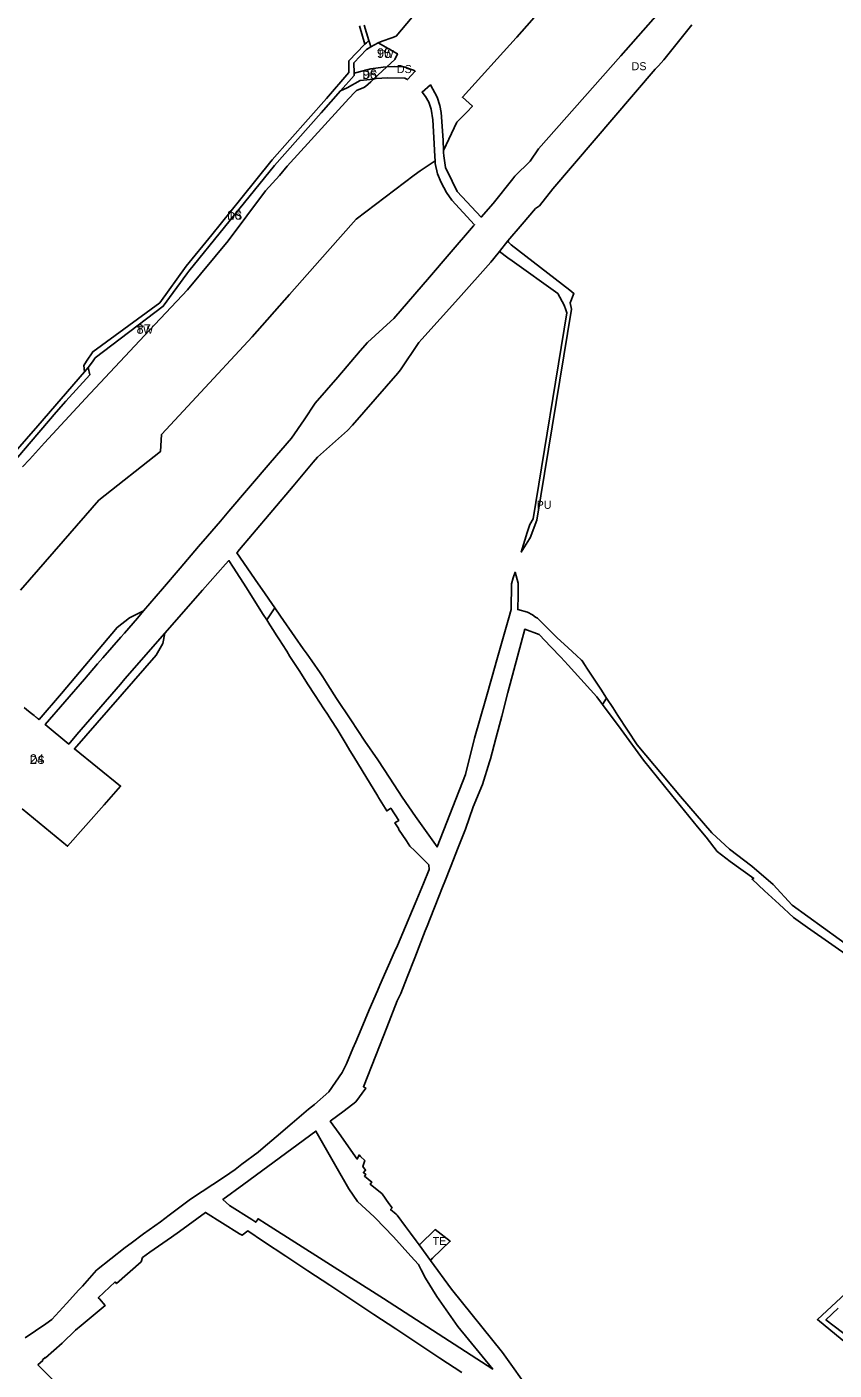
# Model space of a CAD drawing. Extents: x -537034 to -534353, y -1176562 to -1173176.
# Drawn here: x -535789 to -535284, y -1175264 to -1174424 of the extents above; entities that cross this region are included whole.
import ezdxf

# ---------------------------------------------------------------- set-up
doc = ezdxf.new("R2010")
doc.units = 0
for name, color, linetype in [('90320013', 7, 'Continuous'), ('90320023', 7, 'Continuous'), ('90330013', 7, 'Continuous'), ('90390023', 7, 'Continuous'), ('90400013', 7, 'Continuous'), ('90450013', 7, 'Continuous'), ('ID_navrh', 7, 'Continuous')]:
    doc.layers.add(name, color=color, linetype=linetype)

msp = doc.modelspace()

# ---------------------------------------------------------------- linework, layer by layer
at = {"layer": '90320013'}
for points in [[(-535373.49, -1174423.05), (-535390.89, -1174444.84), (-535394.37, -1174448.56), (-535396.32, -1174450.64), (-535460.36, -1174525.57), (-535468.67, -1174536.04), (-535471.15, -1174537.77), (-535479.55, -1174547.52), (-535488.59, -1174558.02), (-535493.78, -1174564.65), (-535497.25, -1174569.07), (-535499.11, -1174571.32), (-535519.4, -1174593.91), (-535542.3, -1174619.4), (-535544.16, -1174621.48), (-535555.54, -1174638.64), (-535557.37, -1174640.72), (-535585.75, -1174673.06), (-535588.72, -1174676.44), (-535607.59, -1174693.18), (-535610.27, -1174696.36), (-535622.79, -1174711.22), (-535648.09, -1174741.22), (-535656.23, -1174750.88), (-535657.72, -1174752.65), (-535658.06, -1174752.99), (-535644.71, -1174772.21), (-535642.13, -1174775.92), (-535634.25, -1174787.25), (-535639.25, -1174794.86), (-535641.48, -1174791.36), (-535642.89, -1174789.15), (-535652.03, -1174774.81), (-535656.11, -1174768.41), (-535660.29, -1174761.86), (-535662.91, -1174757.75), (-535665.15, -1174759.95), (-535679.38, -1174776.21), (-535702.92, -1174803.1), (-535727.94, -1174831.68), (-535730.8, -1174834.95), (-535757.93, -1174866.46), (-535763.09, -1174872.45), (-535777.81, -1174860.26), (-535753.32, -1174831.89), (-535745.05, -1174822.31), (-535741.81, -1174818.61), (-535730.54, -1174805.7), (-535728.28, -1174803.12), (-535720.01, -1174793.65), (-535716.26, -1174789.26), (-535704.49, -1174775.48), (-535693.46, -1174762.57), (-535681.87, -1174749), (-535676.25, -1174742.42), (-535670.89, -1174736.17), (-535668.24, -1174733.08), (-535662.9, -1174726.86), (-535637.08, -1174696.76), (-535623.74, -1174681.22), (-535615.96, -1174669.8), (-535608.9, -1174659.44), (-535594.83, -1174643.09), (-535580.76, -1174626.75), (-535576.31, -1174621.58), (-535561.88, -1174608.41), (-535559.75, -1174606.46), (-535537.48, -1174580.61), (-535525.17, -1174566.32), (-535509.96, -1174548.62), (-535509.32, -1174547.89), (-535523.54, -1174532.47), (-535526.78, -1174527.73), (-535530.21, -1174521.58), (-535532.6, -1174516.01), (-535533.96, -1174509.74), (-535534.01, -1174508.81), (-535534.06, -1174508.07), (-535534.22, -1174505.2), (-535534.89, -1174493.42), (-535535.53, -1174482.27), (-535536.55, -1174475.76), (-535537.97, -1174471.29), (-535539.98, -1174467.86), (-535542.19, -1174465.03), (-535536.95, -1174460.5), (-535532.81, -1174468.18), (-535531.1, -1174473.31), (-535530.16, -1174477.81), (-535528.98, -1174495.04), (-535528.74, -1174501.56), (-535528.7, -1174502.71), (-535528.62, -1174504.76), (-535527.55, -1174512.19), (-535523.26, -1174520.67), (-535520.16, -1174527.13), (-535505.18, -1174543.16), (-535497.79, -1174534.64), (-535485.44, -1174519.17), (-535484.19, -1174517.6), (-535474.62, -1174508.21), (-535469.32, -1174500.48), (-535417.86, -1174442.33), (-535383.65, -1174403.46)], [(-535233.44, -1175034.37), (-535301.06, -1174986.97), (-535309.83, -1174980.83), (-535318.81, -1174972.57), (-535327.96, -1174964.15), (-535335.79, -1174956.95), (-535334.8, -1174956.49), (-535349.55, -1174945.71), (-535357.59, -1174939.56), (-535364.5, -1174930.66), (-535369.87, -1174924.08), (-535386.22, -1174904.06), (-535403.69, -1174882.59), (-535417.66, -1174863.32), (-535429.42, -1174847.62), (-535426.85, -1174843.66), (-535422.98, -1174849.53), (-535419.7, -1174854.51), (-535407.58, -1174872.88), (-535380.6, -1174905.1), (-535360.99, -1174927.82), (-535349.99, -1174938.08), (-535335.96, -1174948.68), (-535322.59, -1174960.24), (-535310.83, -1174973.08), (-535242.13, -1175022.75)], [(-535271.33, -1175251.31), (-535290.22, -1175235.89), (-535294.94, -1175232.04), (-535151.14, -1175098.4)], [(-535281.94, -1175224.98), (-535289.65, -1175232.2), (-535252.39, -1175260.55)]]:
    msp.add_lwpolyline(points, dxfattribs=at)
for points in [[(-535564.26, -1174449.27), (-535559.4, -1174449.08), (-535553.51, -1174449.3), (-535547.44, -1174451.24), (-535546.43, -1174452.03), (-535551.23, -1174457.17), (-535552.99, -1174456.34), (-535563.6, -1174456.02), (-535570.98, -1174456.53), (-535572.49, -1174456.93)], [(-535848.15, -1174755.35), (-535850.97, -1174752.61), (-535848.1, -1174749.3), (-535830.53, -1174729.03), (-535805.04, -1174699.64), (-535782.42, -1174673.55), (-535753.14, -1174639.77), (-535750.85, -1174637.13), (-535749.98, -1174641.67), (-535765, -1174658.05), (-535771.01, -1174665.09), (-535791.35, -1174688.89), (-535816, -1174717.74)]]:
    msp.add_lwpolyline(points, close=True, dxfattribs=at)
at = {"layer": '90320023'}
for points in [[(-535578.34, -1174423.09), (-535575.43, -1174432.79), (-535576.99, -1174434.19), (-535577.9, -1174434.99), (-535581.3, -1174423.66)], [(-535791.04, -1174849.58), (-535789.25, -1174851.01), (-535786.38, -1174853.31), (-535784.8, -1174854.56), (-535783.87, -1174855.31), (-535783.63, -1174855.5), (-535783.42, -1174855.66), (-535782.97, -1174856.02), (-535782.73, -1174856.21), (-535782.58, -1174856.33), (-535782.48, -1174856.41), (-535782.46, -1174856.43), (-535782.43, -1174856.45), (-535782.42, -1174856.46), (-535782.41, -1174856.46), (-535782.4, -1174856.47), (-535782.39, -1174856.48), (-535782.38, -1174856.49), (-535782.36, -1174856.5), (-535782.35, -1174856.51), (-535782.35, -1174856.52), (-535782.34, -1174856.52), (-535782.33, -1174856.53), (-535782.32, -1174856.53), (-535782.32, -1174856.54), (-535782.28, -1174856.57), (-535782.24, -1174856.6), (-535782.17, -1174856.65), (-535782.12, -1174856.69), (-535782.05, -1174856.75), (-535781.92, -1174856.85), (-535781.63, -1174857.08), (-535767.59, -1174840.78), (-535732.8, -1174799.58), (-535725.13, -1174793.48), (-535716.26, -1174789.26), (-535720.01, -1174793.65), (-535728.28, -1174803.12), (-535730.54, -1174805.7), (-535741.81, -1174818.61), (-535745.05, -1174822.31), (-535753.32, -1174831.89), (-535777.81, -1174860.26), (-535763.09, -1174872.45), (-535757.93, -1174866.46), (-535730.8, -1174834.95), (-535727.94, -1174831.68), (-535702.92, -1174803.1), (-535704.27, -1174809.6), (-535708.49, -1174816.79), (-535759.49, -1174875.44), (-535730.65, -1174898.67), (-535740.9, -1174910.33), (-535763.77, -1174936.3), (-535792.27, -1174912.94)]]:
    msp.add_lwpolyline(points, dxfattribs=at)
for points in [[(-535577.9, -1174434.99), (-535576.99, -1174434.19), (-535575.43, -1174432.79), (-535574.87, -1174434.67), (-535574.22, -1174436.82), (-535576.86, -1174438.35), (-535584.81, -1174446.74), (-535584.57, -1174453.18), (-535584.51, -1174454.64), (-535593.09, -1174464.3), (-535605.25, -1174478.01), (-535634.43, -1174510.88), (-535665.63, -1174549.39), (-535687.99, -1174576.99), (-535689.14, -1174578.56), (-535703.99, -1174598.8), (-535746.46, -1174631.01), (-535748.27, -1174633.53), (-535750.85, -1174637.13), (-535753.14, -1174639.77), (-535753.67, -1174635.81), (-535752.02, -1174633.19), (-535748.07, -1174627.29), (-535706.15, -1174596.66), (-535689.66, -1174573.74), (-535673.59, -1174554.12), (-535655.58, -1174531.8), (-535635.91, -1174507.3), (-535624.77, -1174494.76), (-535601.81, -1174468.98), (-535587.88, -1174452.82), (-535587.95, -1174445.5), (-535578.18, -1174435.24)], [(-535593.09, -1174464.3), (-535584.51, -1174454.64), (-535584.57, -1174453.18), (-535574.22, -1174450.5), (-535566.58, -1174449.37), (-535564.26, -1174449.27), (-535572.49, -1174456.93), (-535580.79, -1174457.86), (-535589.02, -1174462.38)]]:
    msp.add_lwpolyline(points, close=True, dxfattribs=at)
at = {"layer": '90330013'}
for points in [[(-535411.51, -1174349.5), (-535482.99, -1174430.74), (-535483.27, -1174431.05), (-535516.92, -1174468.22), (-535510.67, -1174473.73), (-535514.27, -1174477.46), (-535517.93, -1174481.25), (-535520.47, -1174483.88), (-535528.74, -1174501.56), (-535528.98, -1174495.04), (-535530.16, -1174477.81), (-535531.1, -1174473.31), (-535532.81, -1174468.18), (-535536.95, -1174460.5), (-535542.19, -1174465.03), (-535539.98, -1174467.86), (-535537.97, -1174471.29), (-535536.55, -1174475.76), (-535535.53, -1174482.27), (-535534.89, -1174493.42), (-535534.22, -1174505.2), (-535534.06, -1174508.07), (-535535.15, -1174508.78), (-535543.45, -1174514.17), (-535547.02, -1174516.87), (-535583.39, -1174544.45), (-535601.2, -1174564.58), (-535625.08, -1174591.58), (-535648.45, -1174618), (-535683.3, -1174655.54), (-535704.99, -1174678.9), (-535705.75, -1174689.68), (-535744.28, -1174720.12), (-535766.49, -1174745.54), (-535793.3, -1174776.23)], [(-535791.89, -1174699.19), (-535787.66, -1174694.59), (-535778.18, -1174684.25), (-535752.69, -1174656.44), (-535712.62, -1174613.88), (-535688.83, -1174588.61), (-535663.42, -1174557.88), (-535640, -1174526.8), (-535631.37, -1174517.08), (-535626.48, -1174511.34), (-535587.97, -1174469.09), (-535584.26, -1174465.02), (-535583.58, -1174464.36), (-535583.18, -1174464.05), (-535582.05, -1174463.57), (-535578.67, -1174462.15), (-535577.56, -1174461.5), (-535575.88, -1174460.08), (-535574.25, -1174458.61), (-535572.49, -1174456.93), (-535570.98, -1174456.53), (-535563.6, -1174456.02), (-535552.99, -1174456.34), (-535551.23, -1174457.17), (-535546.43, -1174452.03), (-535547.44, -1174451.24), (-535553.51, -1174449.3), (-535559.4, -1174449.08), (-535564.26, -1174449.27), (-535559.27, -1174444.63), (-535557.53, -1174441.09), (-535569.6, -1174434.13), (-535567.11, -1174433.24), (-535561.07, -1174431.1), (-535558.43, -1174430.17), (-535520.55, -1174385.1)]]:
    msp.add_lwpolyline(points, dxfattribs=at)
at = {"layer": '90390023'}
msp.add_lwpolyline([(-535569.6, -1174434.13), (-535557.53, -1174441.09), (-535559.27, -1174444.63), (-535564.26, -1174449.27), (-535566.58, -1174449.37), (-535574.22, -1174450.5), (-535584.57, -1174453.18), (-535584.81, -1174446.74), (-535576.86, -1174438.35), (-535574.22, -1174436.82)], close=True, dxfattribs=at)
msp.add_lwpolyline([(-535791.35, -1174688.89), (-535771.01, -1174665.09), (-535765, -1174658.05), (-535749.98, -1174641.67), (-535750.85, -1174637.13), (-535748.27, -1174633.53), (-535746.46, -1174631.01), (-535703.99, -1174598.8), (-535689.14, -1174578.56), (-535687.99, -1174576.99), (-535665.63, -1174549.39), (-535634.43, -1174510.88), (-535605.25, -1174478.01), (-535593.09, -1174464.3), (-535589.02, -1174462.38), (-535580.79, -1174457.86), (-535572.49, -1174456.93), (-535574.25, -1174458.61), (-535575.88, -1174460.08), (-535577.56, -1174461.5), (-535578.67, -1174462.15), (-535582.05, -1174463.57), (-535583.18, -1174464.05), (-535583.58, -1174464.36), (-535584.26, -1174465.02), (-535587.97, -1174469.09), (-535626.48, -1174511.34), (-535631.37, -1174517.08), (-535640, -1174526.8), (-535663.42, -1174557.88), (-535688.83, -1174588.61), (-535712.62, -1174613.88), (-535752.69, -1174656.44), (-535778.18, -1174684.25), (-535787.66, -1174694.59), (-535791.89, -1174699.19)], dxfattribs=at)
at = {"layer": '90400013'}
msp.add_lwpolyline([(-535544, -1175185.41), (-535543.63, -1175185.05), (-535533.98, -1175175.85), (-535528.3, -1175180.21), (-535524.56, -1175183.07), (-535535.61, -1175193.76), (-535536.94, -1175195.05)], close=True, dxfattribs=at)
at = {"layer": '90450013'}
for points in [[(-535493.78, -1174564.65), (-535488.59, -1174558.02), (-535488.13, -1174558.8), (-535486.55, -1174560.39), (-535449.87, -1174588.74), (-535447.21, -1174590.8), (-535449.55, -1174596.67), (-535448.76, -1174600.74), (-535470.32, -1174732.58), (-535474.51, -1174743.6), (-535474.91, -1174744.23), (-535480.16, -1174752.5), (-535476.38, -1174740.24), (-535474.82, -1174735.18), (-535472.77, -1174731.72), (-535451.68, -1174602.89), (-535452.36, -1174600.98), (-535453.38, -1174598.07), (-535457.32, -1174590.95), (-535485.78, -1174570.42), (-535488.44, -1174568.5)], [(-535566.31, -1175218.99), (-535497.94, -1175262.97), (-535519.74, -1175236.28), (-535532.89, -1175217.54), (-535539.95, -1175206.12), (-535542.76, -1175201.05), (-535544.47, -1175197.66), (-535549.17, -1175192.34), (-535560.06, -1175180.33), (-535571.43, -1175168.45), (-535572.02, -1175167.9), (-535582.44, -1175158.32), (-535587.95, -1175150.4), (-535596.15, -1175136.23), (-535608.49, -1175114.27), (-535653.67, -1175147.46), (-535666.66, -1175157.01), (-535662.51, -1175160.8), (-535648.64, -1175169.59), (-535646.12, -1175171.19), (-535644.73, -1175169.05), (-535639.35, -1175172.43)]]:
    msp.add_lwpolyline(points, close=True, dxfattribs=at)
for points in [[(-535790.26, -1175243.55), (-535777.3, -1175234.67), (-535773.71, -1175232.01), (-535764.48, -1175221.91), (-535756.83, -1175213.54), (-535754.56, -1175211.18), (-535745.63, -1175201.15), (-535727.8, -1175187.08), (-535724.11, -1175184.28), (-535716.26, -1175178.45), (-535705.75, -1175170.95), (-535700.24, -1175166.8), (-535686.95, -1175156.86), (-535665.74, -1175142.82), (-535659.09, -1175138.21), (-535654.82, -1175135.04), (-535644.56, -1175127.45), (-535641.46, -1175124.67), (-535633.44, -1175117.95), (-535623.28, -1175109.32), (-535613.07, -1175100.65), (-535609.5, -1175097.65), (-535600.47, -1175089.67), (-535592.06, -1175077.64), (-535589.51, -1175072.29), (-535585.37, -1175062.57), (-535583.61, -1175058.41), (-535580.31, -1175050.64), (-535575.28, -1175038.6), (-535570.05, -1175026.54), (-535568.55, -1175023.14), (-535564.79, -1175014.58), (-535563.16, -1175010.84), (-535559.44, -1175002.32), (-535557.48, -1174998.25), (-535554.11, -1174990.34), (-535546.53, -1174972.14), (-535541.36, -1174959.66), (-535537.73, -1174950.9), (-535537.98, -1174947.95), (-535544.23, -1174941.71), (-535546.72, -1174939.23), (-535549.75, -1174936.2), (-535551.88, -1174932.89), (-535556.88, -1174925.51), (-535556.74, -1174925.41), (-535559.19, -1174921.75), (-535556.71, -1174920.1), (-535561.76, -1174912.57), (-535562.43, -1174913.02), (-535564.23, -1174914.23), (-535569.37, -1174905.78), (-535569.91, -1174904.89), (-535579.58, -1174888.98), (-535584.78, -1174880.43), (-535587.22, -1174876.41), (-535589.59, -1174872.52), (-535595.31, -1174863.13), (-535599.15, -1174857.15), (-535601.36, -1174853.78), (-535603.5, -1174850.51), (-535609.03, -1174842.07), (-535613.82, -1174834.76), (-535618.67, -1174827.14), (-535620.29, -1174824.6), (-535622.72, -1174820.8), (-535624.75, -1174817.61), (-535626.79, -1174814.41), (-535629.43, -1174810.27), (-535631.31, -1174807.32), (-535633.32, -1174804.16), (-535635.04, -1174801.47), (-535637.36, -1174797.83), (-535639.25, -1174794.86), (-535634.25, -1174787.25), (-535630.65, -1174792.43), (-535621.63, -1174805.41), (-535616.44, -1174812.87), (-535614.05, -1174816.31), (-535611.18, -1174820.42), (-535605.97, -1174827.89), (-535604.22, -1174830.39), (-535601.06, -1174835.45), (-535595.7, -1174844), (-535586.76, -1174857.26), (-535577.92, -1174870.68), (-535569.86, -1174882.26), (-535562.23, -1174893.78), (-535554.51, -1174905.59), (-535546.28, -1174917.79), (-535532.81, -1174936.69), (-535515.03, -1174891.45), (-535509.29, -1174868.79), (-535502.2, -1174844.21), (-535498.26, -1174830.11), (-535495.38, -1174819.84), (-535487.92, -1174793.5), (-535486.35, -1174788.34), (-535486.26, -1174772.31), (-535485.11, -1174768.58), (-535484.03, -1174765.07), (-535481.97, -1174771.97), (-535482.11, -1174779.15), (-535482.28, -1174788.36), (-535476.14, -1174789.91), (-535473.12, -1174791.77), (-535471.13, -1174793.04), (-535470.76, -1174793.28), (-535470.08, -1174793.7), (-535463.55, -1174800.18), (-535460.66, -1174803.04), (-535457.94, -1174805.74), (-535450.76, -1174812.35), (-535445.58, -1174817.12), (-535442.45, -1174820), (-535441.32, -1174821.49), (-535441.42, -1174821.56), (-535437.91, -1174826.88), (-535433.77, -1174833.16), (-535430.46, -1174838.18), (-535426.85, -1174843.66), (-535429.42, -1174847.62), (-535432.94, -1174842.91), (-535450.8, -1174823.21), (-535455.4, -1174818.14), (-535461.69, -1174811.61), (-535468.9, -1174804.05), (-535478, -1174800.72), (-535484.71, -1174826.3), (-535488.46, -1174840.22), (-535492.36, -1174855.04), (-535496.02, -1174869.01), (-535499.42, -1174881.69), (-535499.93, -1174883.58), (-535504.38, -1174897.75), (-535510.22, -1174911.73), (-535515.1, -1174925.61), (-535519.5, -1174937.04), (-535524.48, -1174949.41), (-535528, -1174958.32), (-535529.43, -1174961.86), (-535533.97, -1174973.41), (-535534.83, -1174975.61), (-535539.05, -1174986.29), (-535540.21, -1174989.22), (-535546.78, -1175005.96), (-535551.53, -1175018.08), (-535555.5, -1175028.24), (-535557.71, -1175032.97), (-535564.11, -1175049.59), (-535571.04, -1175067), (-535578.84, -1175086.54), (-535577.4, -1175087.39), (-535583.63, -1175096.02), (-535590.83, -1175101.63), (-535599.53, -1175108.17), (-535593.91, -1175115.7), (-535582.72, -1175131.73), (-535581.52, -1175129.13), (-535580.6, -1175130.05), (-535578.01, -1175132.61), (-535579.11, -1175136.3), (-535577.52, -1175138.59), (-535578.81, -1175140.18), (-535577.41, -1175141.32), (-535578.17, -1175142.35), (-535573.67, -1175146.12), (-535574.65, -1175147.34), (-535567.21, -1175153.41), (-535567.04, -1175153.55), (-535562.98, -1175159.5), (-535560.93, -1175162.29), (-535561.81, -1175163.35), (-535558.29, -1175166.26), (-535557.63, -1175166.8), (-535552.48, -1175173.84), (-535549.4, -1175178.04), (-535545.88, -1175182.84), (-535544, -1175185.41), (-535536.94, -1175195.05), (-535523.78, -1175213.02), (-535491.93, -1175252.57), (-535473.76, -1175278)], [(-535517.26, -1175265.22), (-535531.03, -1175256.12), (-535544.81, -1175247.01), (-535558.58, -1175237.91), (-535572.35, -1175228.81), (-535586.12, -1175219.7), (-535599.89, -1175210.6), (-535613.67, -1175201.5), (-535627.44, -1175192.39), (-535641.21, -1175183.29), (-535651.2, -1175176.69), (-535654.67, -1175179.34), (-535656.21, -1175178.38), (-535677.63, -1175165.08), (-535693.75, -1175176.92), (-535698.8, -1175180.63), (-535712.31, -1175190), (-535717.02, -1175193.27), (-535717.81, -1175195.96), (-535733.14, -1175209.55), (-535734.1, -1175208.57), (-535744.64, -1175218.43), (-535743.81, -1175219.11), (-535740.31, -1175223.34), (-535755.3, -1175235.82), (-535758.84, -1175238.77), (-535767.23, -1175246.76), (-535777.54, -1175256.04), (-535777.63, -1175256.13), (-535777.9, -1175255.83), (-535779.49, -1175257.27), (-535779.22, -1175257.56), (-535782.33, -1175260.36), (-535781.5, -1175261.2), (-535770.83, -1175272)]]:
    msp.add_lwpolyline(points, dxfattribs=at)

# ---------------------------------------------------------------- texts
at = {"layer": '90320013'}
msp.add_text('DS', height=5, rotation=360, dxfattribs=at).set_placement((-535411.14, -1174451.34))
msp.add_text('DS', height=5, dxfattribs=at).set_placement((-535557.93, -1174453.13))
at = {"layer": '90320023'}
msp.add_text('DS', height=5, dxfattribs=at).set_placement((-535579.37, -1174456.78))
for rotation, p in [(360, (-535663.95, -1174544.74)), (0, (-535787.45, -1174884.8))]:
    msp.add_text('DS', height=5, rotation=rotation, dxfattribs=at).set_placement(p)
at = {"layer": '90390023'}
for p in [(-535570.34, -1174443.66), (-535720.68, -1174616.04)]:
    msp.add_text('TW', height=5, rotation=0, dxfattribs=at).set_placement(p)
at = {"layer": '90400013'}
msp.add_text('TE', height=5, rotation=0, dxfattribs=at).set_placement((-535535.5, -1175185.45))
at = {"layer": '90450013'}
msp.add_text('PU', height=5, rotation=360, dxfattribs=at).set_placement((-535470.5, -1174725.43))
at = {"layer": 'ID_navrh'}
for s, rotation, p in [('95', 360, (-535570.34, -1174443.66)), ('96', 360, (-535579.37, -1174456.78)), ('16', 0, (-535663.95, -1174544.74)), ('87', 360, (-535720.68, -1174616.04)), ('24', 0, (-535787.45, -1174884.8))]:
    msp.add_text(s, height=6, rotation=rotation, dxfattribs=at).set_placement(p)

doc.saveas('drawing.dxf')
